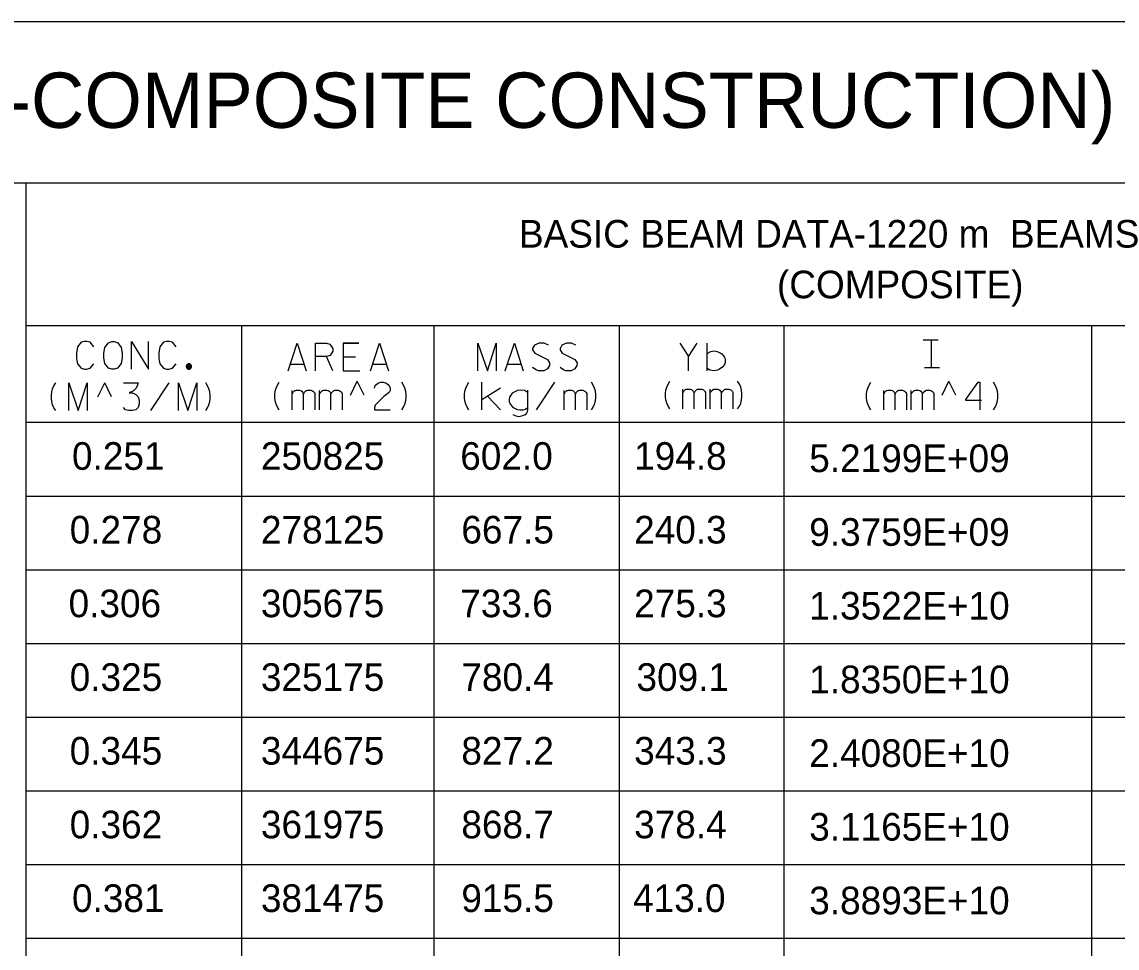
# Model space of a CAD drawing. Extents: x 635698 to 639877, y 296617 to 300175.
# Drawn here: x 636088.1 to 636207, y 299938.2 to 300038.7 of the extents above; entities that cross this region are included whole.
import ezdxf

# ---------------------------------------------------------------- set-up
doc = ezdxf.new("R2010")
doc.units = 0
doc.layers.add('2', color=7, linetype='Continuous')

msp = doc.modelspace()

# ---------------------------------------------------------------- linework, layer by layer
at = {"layer": '2'}
for p, q in [((636461.71, 300038.71), (635698.21, 300038.71)), ((636454.58, 300021.21), (635703.83, 300021.21)), ((636088.58, 300021.21), (636088.58, 299883.21)), ((636270.96, 300005.71), (636088.58, 300005.71)), ((636111.96, 300005.71), (636111.96, 299883.21)), ((636132.83, 300005.71), (636132.83, 299883.21)), ((636152.96, 300005.71), (636152.96, 299883.21)), ((636170.83, 300005.71), (636170.83, 299883.21)), ((636204.21, 300005.71), (636204.21, 299883.21)), ((636185.96, 300004.21), (636187.58, 300004.21)), ((636186.08, 300001.21), (636187.71, 300001.21)), ((636096.38, 299998.02), (636097.13, 299999.52)), ((636097.88, 299998.02), (636097.13, 299999.52)), ((636123.79, 299998.2), (636124.54, 299999.7)), ((636125.29, 299998.2), (636124.54, 299999.7)), ((636187.99, 299998.2), (636188.74, 299999.7)), ((636189.49, 299998.2), (636188.74, 299999.7)), ((636270.96, 299995.21), (636088.58, 299995.21)), ((636270.96, 299987.21), (636088.58, 299987.21)), ((636270.96, 299979.21), (636088.58, 299979.21)), ((636270.96, 299971.21), (636088.58, 299971.21)), ((636270.96, 299963.21), (636088.58, 299963.21)), ((636270.96, 299955.21), (636088.58, 299955.21)), ((636270.96, 299947.21), (636088.58, 299947.21)), ((636270.96, 299939.21), (636088.58, 299939.21))]:
    msp.add_line(p, q, dxfattribs=at)
for points in [[(636095.94, 300003.43), (636095.56, 300003.93), (636095.18, 300004.02), (636094.92, 300004.02), (636094.57, 300003.93), (636094.17, 300003.43), (636094.07, 300002.77), (636094.07, 300002.41), (636094.07, 300002.18), (636094.1, 300001.97), (636094.17, 300001.59), (636094.57, 300001.12), (636094.92, 300001.02), (636095.14, 300001.02), (636095.54, 300001.12), (636095.94, 300001.59)], [(636097.9, 300004.02), (636098.14, 300004.02), (636098.54, 300003.86), (636098.92, 300003.36), (636099.01, 300002.77), (636099.01, 300002.23), (636098.92, 300001.63), (636098.51, 300001.14), (636098.14, 300001.02), (636097.9, 300001.02), (636097.55, 300001.14), (636097.14, 300001.63), (636097.05, 300002.23), (636097.05, 300002.77), (636097.14, 300003.38), (636097.55, 300003.88), (636097.9, 300004.02)], [(636100.03, 300001.02), (636100.03, 300004.02), (636101.89, 300001.02), (636101.89, 300004.02)], [(636104.87, 300003.43), (636104.49, 300003.93), (636104.11, 300004.02), (636103.85, 300004.02), (636103.5, 300003.93), (636103.1, 300003.43), (636103, 300002.77), (636103, 300002.41), (636103, 300002.18), (636103.03, 300001.97), (636103.1, 300001.59), (636103.5, 300001.12), (636103.85, 300001.02), (636104.07, 300001.02), (636104.47, 300001.12), (636104.87, 300001.59)], [(636117.03, 300000.84), (636118.02, 300003.84), (636118.99, 300000.84)], [(636120.01, 300000.84), (636120.01, 300003.84), (636121.21, 300003.84), (636121.57, 300003.72), (636121.87, 300003.25), (636121.87, 300002.97), (636121.59, 300002.49), (636121.21, 300002.38), (636120.01, 300002.38)], [(636124.71, 300003.84), (636122.99, 300003.84), (636122.99, 300000.84), (636124.83, 300000.84)], [(636122.99, 300003.84), (636124.71, 300003.84)], [(636125.96, 300000.84), (636126.95, 300003.84), (636127.92, 300000.84)], [(636137.61, 300000.84), (636137.61, 300003.84), (636138.65, 300000.84), (636139.62, 300003.84), (636139.62, 300000.84)], [(636140.59, 300000.84), (636141.58, 300003.84), (636142.55, 300000.84)], [(636145.29, 300003.63), (636144.81, 300003.84), (636144.27, 300003.84), (636143.77, 300003.63), (636143.56, 300003.25), (636143.56, 300003.11), (636143.8, 300002.75), (636145.17, 300002.05), (636145.4, 300001.71), (636145.38, 300001.43), (636145.17, 300001.05), (636144.77, 300000.84), (636144.2, 300000.84), (636143.94, 300000.94), (636143.56, 300001.2)], [(636148.26, 300003.63), (636147.79, 300003.84), (636147.25, 300003.84), (636146.75, 300003.63), (636146.54, 300003.25), (636146.54, 300003.11), (636146.77, 300002.75), (636148.14, 300002.05), (636148.38, 300001.71), (636148.36, 300001.43), (636148.14, 300001.05), (636147.74, 300000.84), (636147.18, 300000.84), (636146.92, 300000.94), (636146.54, 300001.2)], [(636159.54, 300003.84), (636160.48, 300002.4), (636161.43, 300003.84)], [(636162.51, 300000.84), (636162.51, 300003.84)], [(636186.49, 300004.21), (636187.2, 300004.21)], [(636186.85, 300001.21), (636186.85, 300004.21)], [(636121.87, 300000.84), (636121.19, 300002.38)], [(636122.99, 300002.35), (636124.34, 300002.35)], [(636122.99, 300002.35), (636124.34, 300002.35)], [(636160.48, 300000.84), (636160.48, 300002.4)], [(636162.51, 300002.73), (636162.89, 300002.94), (636163.27, 300002.99), (636163.6, 300002.94), (636163.91, 300002.8), (636164.1, 300002.68), (636164.29, 300002.47), (636164.38, 300002.28), (636164.47, 300002.12), (636164.47, 300001.67), (636164.33, 300001.41), (636164.21, 300001.27), (636163.86, 300001.01), (636163.62, 300000.89), (636163.27, 300000.84), (636162.8, 300000.89), (636162.51, 300001.08)], [(636106.55, 300001.31), (636106.55, 300001.34), (636106.54, 300001.36), (636106.53, 300001.39), (636106.52, 300001.42), (636106.51, 300001.45), (636106.49, 300001.47), (636106.48, 300001.5), (636106.45, 300001.52), (636106.43, 300001.54), (636106.41, 300001.55), (636106.38, 300001.57), (636106.35, 300001.58), (636106.32, 300001.58), (636106.29, 300001.59), (636106.26, 300001.59), (636106.23, 300001.59), (636106.2, 300001.58), (636106.18, 300001.58), (636106.15, 300001.57), (636106.12, 300001.55), (636106.1, 300001.54), (636106.07, 300001.52), (636106.05, 300001.5), (636106.03, 300001.47), (636106.02, 300001.45), (636106, 300001.42), (636105.99, 300001.39), (636105.99, 300001.36), (636105.98, 300001.34), (636105.98, 300001.31), (636105.98, 300001.28), (636105.99, 300001.25), (636105.99, 300001.22), (636106, 300001.19), (636106.02, 300001.16), (636106.03, 300001.14), (636106.05, 300001.11), (636106.07, 300001.09), (636106.1, 300001.07), (636106.12, 300001.06), (636106.15, 300001.05), (636106.18, 300001.03), (636106.2, 300001.03), (636106.23, 300001.02), (636106.26, 300001.02), (636106.29, 300001.02), (636106.32, 300001.03), (636106.35, 300001.03), (636106.38, 300001.05), (636106.41, 300001.06), (636106.43, 300001.07), (636106.45, 300001.09), (636106.48, 300001.11), (636106.49, 300001.14), (636106.51, 300001.16), (636106.52, 300001.19), (636106.53, 300001.22), (636106.54, 300001.25), (636106.55, 300001.28), (636106.55, 300001.31)], [(636106.49, 300001.31), (636106.49, 300001.33), (636106.48, 300001.35), (636106.48, 300001.38), (636106.47, 300001.4), (636106.46, 300001.42), (636106.45, 300001.44), (636106.43, 300001.46), (636106.41, 300001.47), (636106.4, 300001.49), (636106.38, 300001.5), (636106.36, 300001.51), (636106.33, 300001.52), (636106.31, 300001.53), (636106.29, 300001.53), (636106.26, 300001.53), (636106.24, 300001.53), (636106.22, 300001.53), (636106.19, 300001.52), (636106.17, 300001.51), (636106.15, 300001.5), (636106.13, 300001.49), (636106.11, 300001.47), (636106.1, 300001.46), (636106.08, 300001.44), (636106.07, 300001.42), (636106.06, 300001.4), (636106.05, 300001.38), (636106.04, 300001.35), (636106.04, 300001.33), (636106.04, 300001.31), (636106.04, 300001.28), (636106.04, 300001.26), (636106.05, 300001.24), (636106.06, 300001.21), (636106.07, 300001.19), (636106.08, 300001.17), (636106.1, 300001.16), (636106.11, 300001.14), (636106.13, 300001.12), (636106.15, 300001.11), (636106.17, 300001.1), (636106.19, 300001.09), (636106.22, 300001.09), (636106.24, 300001.08), (636106.26, 300001.08), (636106.29, 300001.08), (636106.31, 300001.09), (636106.33, 300001.09), (636106.36, 300001.1), (636106.38, 300001.11), (636106.4, 300001.12), (636106.41, 300001.14), (636106.43, 300001.16), (636106.45, 300001.17), (636106.46, 300001.19), (636106.47, 300001.21), (636106.48, 300001.24), (636106.48, 300001.26), (636106.49, 300001.28), (636106.49, 300001.31)], [(636106.43, 300001.31), (636106.43, 300001.32), (636106.42, 300001.34), (636106.42, 300001.36), (636106.41, 300001.37), (636106.41, 300001.39), (636106.4, 300001.4), (636106.39, 300001.42), (636106.37, 300001.43), (636106.36, 300001.44), (636106.35, 300001.45), (636106.33, 300001.46), (636106.31, 300001.46), (636106.3, 300001.47), (636106.28, 300001.47), (636106.26, 300001.47), (636106.25, 300001.47), (636106.23, 300001.47), (636106.21, 300001.46), (636106.2, 300001.46), (636106.18, 300001.45), (636106.17, 300001.44), (636106.15, 300001.43), (636106.14, 300001.42), (636106.13, 300001.4), (636106.12, 300001.39), (636106.11, 300001.37), (636106.11, 300001.36), (636106.1, 300001.34), (636106.1, 300001.32), (636106.1, 300001.31), (636106.1, 300001.29), (636106.1, 300001.27), (636106.11, 300001.25), (636106.11, 300001.24), (636106.12, 300001.22), (636106.13, 300001.21), (636106.14, 300001.19), (636106.15, 300001.18), (636106.17, 300001.17), (636106.18, 300001.16), (636106.2, 300001.15), (636106.21, 300001.15), (636106.23, 300001.14), (636106.25, 300001.14), (636106.26, 300001.14), (636106.28, 300001.14), (636106.3, 300001.14), (636106.31, 300001.15), (636106.33, 300001.15), (636106.35, 300001.16), (636106.36, 300001.17), (636106.37, 300001.18), (636106.39, 300001.19), (636106.4, 300001.21), (636106.41, 300001.22), (636106.41, 300001.24), (636106.42, 300001.25), (636106.42, 300001.27), (636106.43, 300001.29), (636106.43, 300001.31)], [(636106.37, 300001.31), (636106.37, 300001.32), (636106.37, 300001.33), (636106.36, 300001.34), (636106.36, 300001.35), (636106.35, 300001.36), (636106.35, 300001.37), (636106.34, 300001.38), (636106.33, 300001.38), (636106.33, 300001.39), (636106.32, 300001.4), (636106.31, 300001.4), (636106.3, 300001.41), (636106.29, 300001.41), (636106.27, 300001.41), (636106.26, 300001.41), (636106.25, 300001.41), (636106.24, 300001.41), (636106.23, 300001.41), (636106.22, 300001.4), (636106.21, 300001.4), (636106.2, 300001.39), (636106.19, 300001.38), (636106.19, 300001.38), (636106.18, 300001.37), (636106.17, 300001.36), (636106.17, 300001.35), (636106.16, 300001.34), (636106.16, 300001.33), (636106.16, 300001.32), (636106.16, 300001.31), (636106.16, 300001.29), (636106.16, 300001.28), (636106.16, 300001.27), (636106.17, 300001.26), (636106.17, 300001.25), (636106.18, 300001.24), (636106.19, 300001.24), (636106.19, 300001.23), (636106.2, 300001.22), (636106.21, 300001.21), (636106.22, 300001.21), (636106.23, 300001.21), (636106.24, 300001.2), (636106.25, 300001.2), (636106.26, 300001.2), (636106.27, 300001.2), (636106.29, 300001.2), (636106.3, 300001.21), (636106.31, 300001.21), (636106.32, 300001.21), (636106.33, 300001.22), (636106.33, 300001.23), (636106.34, 300001.24), (636106.35, 300001.24), (636106.35, 300001.25), (636106.36, 300001.26), (636106.36, 300001.27), (636106.37, 300001.28), (636106.37, 300001.29), (636106.37, 300001.31)], [(636106.31, 300001.31), (636106.31, 300001.31), (636106.31, 300001.31), (636106.31, 300001.32), (636106.3, 300001.32), (636106.3, 300001.33), (636106.3, 300001.33), (636106.3, 300001.34), (636106.29, 300001.34), (636106.29, 300001.34), (636106.29, 300001.34), (636106.28, 300001.35), (636106.28, 300001.35), (636106.27, 300001.35), (636106.27, 300001.35), (636106.26, 300001.35), (636106.26, 300001.35), (636106.25, 300001.35), (636106.25, 300001.35), (636106.25, 300001.35), (636106.24, 300001.34), (636106.24, 300001.34), (636106.23, 300001.34), (636106.23, 300001.34), (636106.23, 300001.33), (636106.22, 300001.33), (636106.22, 300001.32), (636106.22, 300001.32), (636106.22, 300001.31), (636106.22, 300001.31), (636106.22, 300001.31), (636106.22, 300001.3), (636106.22, 300001.3), (636106.22, 300001.29), (636106.22, 300001.29), (636106.22, 300001.28), (636106.23, 300001.28), (636106.23, 300001.28), (636106.23, 300001.27), (636106.24, 300001.27), (636106.24, 300001.27), (636106.25, 300001.26), (636106.25, 300001.26), (636106.25, 300001.26), (636106.26, 300001.26), (636106.26, 300001.26), (636106.27, 300001.26), (636106.27, 300001.26), (636106.28, 300001.26), (636106.28, 300001.26), (636106.29, 300001.27), (636106.29, 300001.27), (636106.29, 300001.27), (636106.3, 300001.28), (636106.3, 300001.28), (636106.3, 300001.28), (636106.3, 300001.29), (636106.31, 300001.29), (636106.31, 300001.3), (636106.31, 300001.3), (636106.31, 300001.31)], [(636117.27, 300001.55), (636118.76, 300001.55)], [(636126.2, 300001.55), (636127.69, 300001.55)], [(636140.82, 300001.55), (636142.31, 300001.55)], [(636186.49, 300001.21), (636187.2, 300001.21)], [(636091.81, 299996.52), (636091.62, 299996.83), (636091.48, 299997.16), (636091.39, 299997.49), (636091.34, 299997.84), (636091.34, 299998.2), (636091.39, 299998.55), (636091.48, 299998.88), (636091.62, 299999.21), (636091.81, 299999.52)], [(636093.22, 299996.52), (636093.22, 299999.52), (636094.26, 299996.52), (636095.22, 299999.52), (636095.22, 299996.52)], [(636099.17, 299999.52), (636100.75, 299999.52), (636100.66, 299999.17), (636100.49, 299998.91), (636100.26, 299998.67), (636099.78, 299998.43), (636100.14, 299998.43), (636100.52, 299998.27), (636100.75, 299998.03), (636100.87, 299997.65), (636100.87, 299997.25), (636100.75, 299996.85), (636100.49, 299996.61), (636100.14, 299996.52), (636099.74, 299996.52), (636099.38, 299996.61), (636099.17, 299996.87)], [(636102.15, 299996.52), (636104.11, 299999.52)], [(636105.12, 299996.52), (636105.12, 299999.52), (636106.16, 299996.52), (636107.13, 299999.52), (636107.13, 299996.52)], [(636108.1, 299996.52), (636108.29, 299996.83), (636108.43, 299997.16), (636108.52, 299997.49), (636108.57, 299997.84), (636108.57, 299998.2), (636108.52, 299998.55), (636108.43, 299998.88), (636108.29, 299999.21), (636108.1, 299999.52)], [(636116.06, 299996.59), (636115.87, 299996.89), (636115.73, 299997.23), (636115.64, 299997.56), (636115.59, 299997.91), (636115.59, 299998.26), (636115.64, 299998.62), (636115.73, 299998.95), (636115.87, 299999.28), (636116.06, 299999.59)], [(636117.47, 299998.34), (636117.51, 299998.38), (636117.56, 299998.48), (636117.77, 299998.69), (636117.84, 299998.71), (636117.94, 299998.74), (636118.27, 299998.74), (636118.41, 299998.69), (636118.51, 299998.62), (636118.6, 299998.52), (636118.67, 299998.36), (636118.69, 299998.31), (636118.74, 299998.38), (636118.79, 299998.48), (636119, 299998.69), (636119.07, 299998.71), (636119.14, 299998.74), (636119.5, 299998.74), (636119.59, 299998.69), (636119.71, 299998.64), (636119.83, 299998.55), (636119.88, 299998.48), (636119.92, 299998.38), (636119.92, 299996.59)], [(636117.47, 299996.59), (636117.47, 299998.71)], [(636120.44, 299998.34), (636120.49, 299998.38), (636120.54, 299998.48), (636120.75, 299998.69), (636120.82, 299998.71), (636120.92, 299998.74), (636121.25, 299998.74), (636121.39, 299998.69), (636121.48, 299998.62), (636121.58, 299998.52), (636121.65, 299998.36), (636121.67, 299998.31), (636121.72, 299998.38), (636121.77, 299998.48), (636121.98, 299998.69), (636122.05, 299998.71), (636122.12, 299998.74), (636122.47, 299998.74), (636122.57, 299998.69), (636122.69, 299998.64), (636122.8, 299998.55), (636122.85, 299998.48), (636122.9, 299998.38), (636122.9, 299996.59)], [(636120.44, 299996.59), (636120.44, 299998.71)], [(636126.4, 299998.97), (636126.49, 299999.26), (636126.75, 299999.49), (636127.1, 299999.59), (636127.36, 299999.59), (636127.72, 299999.49), (636127.98, 299999.23), (636128.1, 299998.97), (636128.1, 299998.71), (636128, 299998.5), (636127.41, 299998.05), (636126.49, 299997.11), (636126.4, 299996.87), (636126.4, 299996.59), (636128.1, 299996.59)], [(636129.37, 299996.59), (636129.56, 299996.89), (636129.7, 299997.23), (636129.8, 299997.56), (636129.85, 299997.91), (636129.85, 299998.26), (636129.8, 299998.62), (636129.7, 299998.95), (636129.56, 299999.28), (636129.37, 299999.59)], [(636136.64, 299996.59), (636136.45, 299996.89), (636136.31, 299997.23), (636136.21, 299997.56), (636136.17, 299997.91), (636136.17, 299998.26), (636136.21, 299998.62), (636136.31, 299998.95), (636136.45, 299999.28), (636136.64, 299999.59)], [(636138.04, 299996.59), (636138.04, 299999.59)], [(636140.07, 299998.97), (636138.04, 299997.67)], [(636143, 299998.48), (636142.7, 299998.69), (636142.25, 299998.74), (636141.92, 299998.71), (636141.35, 299998.41), (636141.07, 299997.98), (636141.02, 299997.74), (636141.02, 299997.51), (636141.11, 299997.23), (636141.37, 299996.94), (636141.59, 299996.78), (636141.89, 299996.63), (636142.18, 299996.59), (636142.55, 299996.61), (636142.79, 299996.68), (636143, 299996.85)], [(636143, 299998.74), (636143, 299996.59), (636142.96, 299996.4), (636142.89, 299996.23), (636142.74, 299996.07), (636142.55, 299995.97), (636142.34, 299995.9), (636142.08, 299995.85), (636141.78, 299995.9), (636141.47, 299996.07)], [(636144, 299996.59), (636145.96, 299999.59)], [(636146.97, 299998.34), (636147.02, 299998.38), (636147.07, 299998.48), (636147.28, 299998.69), (636147.35, 299998.71), (636147.44, 299998.74), (636147.78, 299998.74), (636147.92, 299998.69), (636148.01, 299998.62), (636148.11, 299998.52), (636148.18, 299998.36), (636148.2, 299998.31), (636148.25, 299998.38), (636148.3, 299998.48), (636148.51, 299998.69), (636148.58, 299998.71), (636148.65, 299998.74), (636149, 299998.74), (636149.1, 299998.69), (636149.22, 299998.64), (636149.33, 299998.55), (636149.38, 299998.48), (636149.43, 299998.38), (636149.43, 299996.59)], [(636146.97, 299996.59), (636146.97, 299998.71)], [(636149.95, 299996.59), (636150.14, 299996.89), (636150.28, 299997.23), (636150.37, 299997.56), (636150.42, 299997.91), (636150.42, 299998.26), (636150.37, 299998.62), (636150.28, 299998.95), (636150.14, 299999.28), (636149.95, 299999.59)], [(636158.45, 299996.7), (636158.26, 299997.01), (636158.12, 299997.34), (636158.03, 299997.67), (636157.98, 299998.03), (636157.98, 299998.38), (636158.03, 299998.74), (636158.12, 299999.07), (636158.26, 299999.4), (636158.45, 299999.7)], [(636159.85, 299998.45), (636159.9, 299998.5), (636159.95, 299998.59), (636160.16, 299998.81), (636160.23, 299998.83), (636160.33, 299998.85), (636160.66, 299998.85), (636160.8, 299998.81), (636160.89, 299998.74), (636160.99, 299998.64), (636161.06, 299998.48), (636161.08, 299998.43), (636161.13, 299998.5), (636161.18, 299998.59), (636161.39, 299998.81), (636161.46, 299998.83), (636161.53, 299998.85), (636161.89, 299998.85), (636161.98, 299998.81), (636162.1, 299998.76), (636162.22, 299998.67), (636162.26, 299998.59), (636162.31, 299998.5), (636162.31, 299996.7)], [(636159.85, 299996.7), (636159.85, 299998.83)], [(636162.83, 299998.45), (636162.88, 299998.5), (636162.92, 299998.59), (636163.14, 299998.81), (636163.21, 299998.83), (636163.3, 299998.85), (636163.63, 299998.85), (636163.78, 299998.81), (636163.87, 299998.74), (636163.96, 299998.64), (636164.04, 299998.48), (636164.06, 299998.43), (636164.11, 299998.5), (636164.15, 299998.59), (636164.37, 299998.81), (636164.44, 299998.83), (636164.51, 299998.85), (636164.86, 299998.85), (636164.96, 299998.81), (636165.07, 299998.76), (636165.19, 299998.67), (636165.24, 299998.59), (636165.29, 299998.5), (636165.29, 299996.7)], [(636162.83, 299996.7), (636162.83, 299998.83)], [(636165.81, 299996.7), (636166, 299997.01), (636166.14, 299997.34), (636166.23, 299997.67), (636166.28, 299998.03), (636166.28, 299998.38), (636166.23, 299998.74), (636166.14, 299999.07), (636166, 299999.4), (636165.81, 299999.7)], [(636180.26, 299996.59), (636180.07, 299996.89), (636179.93, 299997.23), (636179.84, 299997.56), (636179.79, 299997.91), (636179.79, 299998.26), (636179.84, 299998.62), (636179.93, 299998.95), (636180.07, 299999.28), (636180.26, 299999.59)], [(636181.66, 299998.34), (636181.71, 299998.38), (636181.76, 299998.48), (636181.97, 299998.69), (636182.04, 299998.71), (636182.14, 299998.74), (636182.47, 299998.74), (636182.61, 299998.69), (636182.7, 299998.62), (636182.8, 299998.52), (636182.87, 299998.36), (636182.89, 299998.31), (636182.94, 299998.38), (636182.99, 299998.48), (636183.2, 299998.69), (636183.27, 299998.71), (636183.34, 299998.74), (636183.7, 299998.74), (636183.79, 299998.69), (636183.91, 299998.64), (636184.03, 299998.55), (636184.07, 299998.48), (636184.12, 299998.38), (636184.12, 299996.59)], [(636181.66, 299996.59), (636181.66, 299998.71)], [(636184.64, 299998.34), (636184.69, 299998.38), (636184.74, 299998.48), (636184.95, 299998.69), (636185.02, 299998.71), (636185.11, 299998.74), (636185.44, 299998.74), (636185.59, 299998.69), (636185.68, 299998.62), (636185.78, 299998.52), (636185.85, 299998.36), (636185.87, 299998.31), (636185.92, 299998.38), (636185.96, 299998.48), (636186.18, 299998.69), (636186.25, 299998.71), (636186.32, 299998.74), (636186.67, 299998.74), (636186.77, 299998.69), (636186.89, 299998.64), (636187, 299998.55), (636187.05, 299998.48), (636187.1, 299998.38), (636187.1, 299996.59)], [(636184.64, 299996.59), (636184.64, 299998.71)], [(636192.29, 299997.63), (636190.59, 299997.63), (636190.59, 299997.74), (636191.92, 299999.59), (636192.08, 299999.59), (636192.08, 299996.59)], [(636193.57, 299996.59), (636193.76, 299996.89), (636193.9, 299997.23), (636194, 299997.56), (636194.04, 299997.91), (636194.04, 299998.26), (636194, 299998.62), (636193.9, 299998.95), (636193.76, 299999.28), (636193.57, 299999.59)], [(636118.69, 299996.59), (636118.69, 299998.34)], [(636121.67, 299996.59), (636121.67, 299998.34)], [(636138.68, 299998.08), (636140.07, 299996.59)], [(636148.2, 299996.59), (636148.2, 299998.34)], [(636161.08, 299996.7), (636161.08, 299998.45)], [(636164.06, 299996.7), (636164.06, 299998.45)], [(636182.89, 299996.59), (636182.89, 299998.34)], [(636185.87, 299996.59), (636185.87, 299998.34)]]:
    msp.add_lwpolyline(points, dxfattribs=at)

# ---------------------------------------------------------------- texts
for s, height, p in [('ADJACENT BOX BEAM DATA (COMPOSITE & NON-COMPOSITE CONSTRUCTION)', 6, (635895.65, 300027.21)), ('BASIC BEAM DATA-1220 m  BEAMS', 3, (636142.08, 300014.21)), ('(COMPOSITE)', 3, (636170.08, 300008.71)), ('0.251', 3, (636093.58, 299990.09)), ('250825', 3, (636114.08, 299990.09)), ('602.0', 3, (636135.71, 299990.09)), ('194.8', 3, (636154.58, 299990.09)), ('5.2199E+09', 3, (636173.58, 299989.84)), ('0.278', 3, (636093.33, 299982.09)), ('278125', 3, (636114.08, 299982.09)), ('667.5', 3, (636135.83, 299982.09)), ('240.3', 3, (636154.58, 299982.09)), ('9.3759E+09', 3, (636173.58, 299981.84)), ('0.306', 3, (636093.21, 299974.09)), ('305675', 3, (636114.08, 299974.09)), ('733.6', 3, (636135.71, 299974.09)), ('275.3', 3, (636154.58, 299974.09)), ('1.3522E+10', 3, (636173.58, 299973.84)), ('0.325', 3, (636093.33, 299966.09)), ('325175', 3, (636114.08, 299966.09)), ('780.4', 3, (636135.83, 299966.09)), ('309.1', 3, (636154.83, 299966.09)), ('1.8350E+10', 3, (636173.58, 299965.84)), ('0.345', 3, (636093.33, 299958.09)), ('344675', 3, (636114.08, 299958.09)), ('827.2', 3, (636135.83, 299958.09)), ('343.3', 3, (636154.58, 299958.09)), ('2.4080E+10', 3, (636173.58, 299957.84)), ('0.362', 3, (636093.33, 299950.09)), ('361975', 3, (636114.08, 299950.09)), ('868.7', 3, (636135.83, 299950.09)), ('378.4', 3, (636154.58, 299950.09)), ('3.1165E+10', 3, (636173.58, 299949.84)), ('0.381', 3, (636093.58, 299942.09)), ('381475', 3, (636114.08, 299942.09)), ('915.5', 3, (636135.83, 299942.09)), ('413.0', 3, (636154.46, 299942.09)), ('3.8893E+10', 3, (636173.58, 299941.84))]:
    msp.add_text(s, height=height, dxfattribs=at).set_placement(p)

doc.saveas('drawing.dxf')
